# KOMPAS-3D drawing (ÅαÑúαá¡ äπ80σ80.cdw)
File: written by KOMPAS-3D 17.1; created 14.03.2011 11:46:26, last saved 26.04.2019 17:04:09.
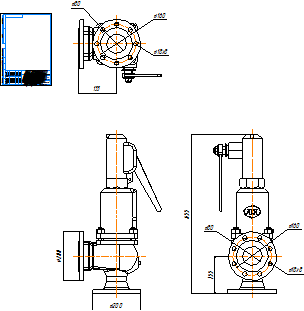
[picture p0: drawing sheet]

Sheet 1: A4, portrait

Title block, sheet 1: name: Прегран Ду80х80; material: Внимание! Данный продукт является объектом авторского права ООО «Торговый Дом АДЛ». / Запрещается изменение, копирование, распространение / (в том числе путем копирования на другие сайты и ресурсы в Интернете) / или любое иное использование информации и объектов без предварительного / согласия правообладателя (ООО «Торговый Дом АДЛ»).; scale: 1:1; sheets: 1; organisation: ООО "Торговый дом АДЛ"; sheet format: A4; stored path: C:\Users\tra\Desktop\2д чертежи\Предохранительные клапаны ПРЕГРАН\ПРЕГРАН 096\ПРЕГРАН КПП 096-03-40\KOMPAS 2D\Прегран Ду80х80.cdw

Views: Спереди 1, Проекционный вид 2, Проекционный вид 3
Dimensions and other numbers on the sheet: 155; 655; 160; 18; 80; 200; 1:1; 1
